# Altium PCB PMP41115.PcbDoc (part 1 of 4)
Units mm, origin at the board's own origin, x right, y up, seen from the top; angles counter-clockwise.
Board outline 97.92 x 43.13 mm, 4 copper layers (Top Layer, Signal Layer 1, Signal Layer 2, Bottom Layer), stack 1.016 mm thick; 168 components, 122 nets, 522 pads, 2459 vias.
Unrouted connection lines stored in the file: 1.
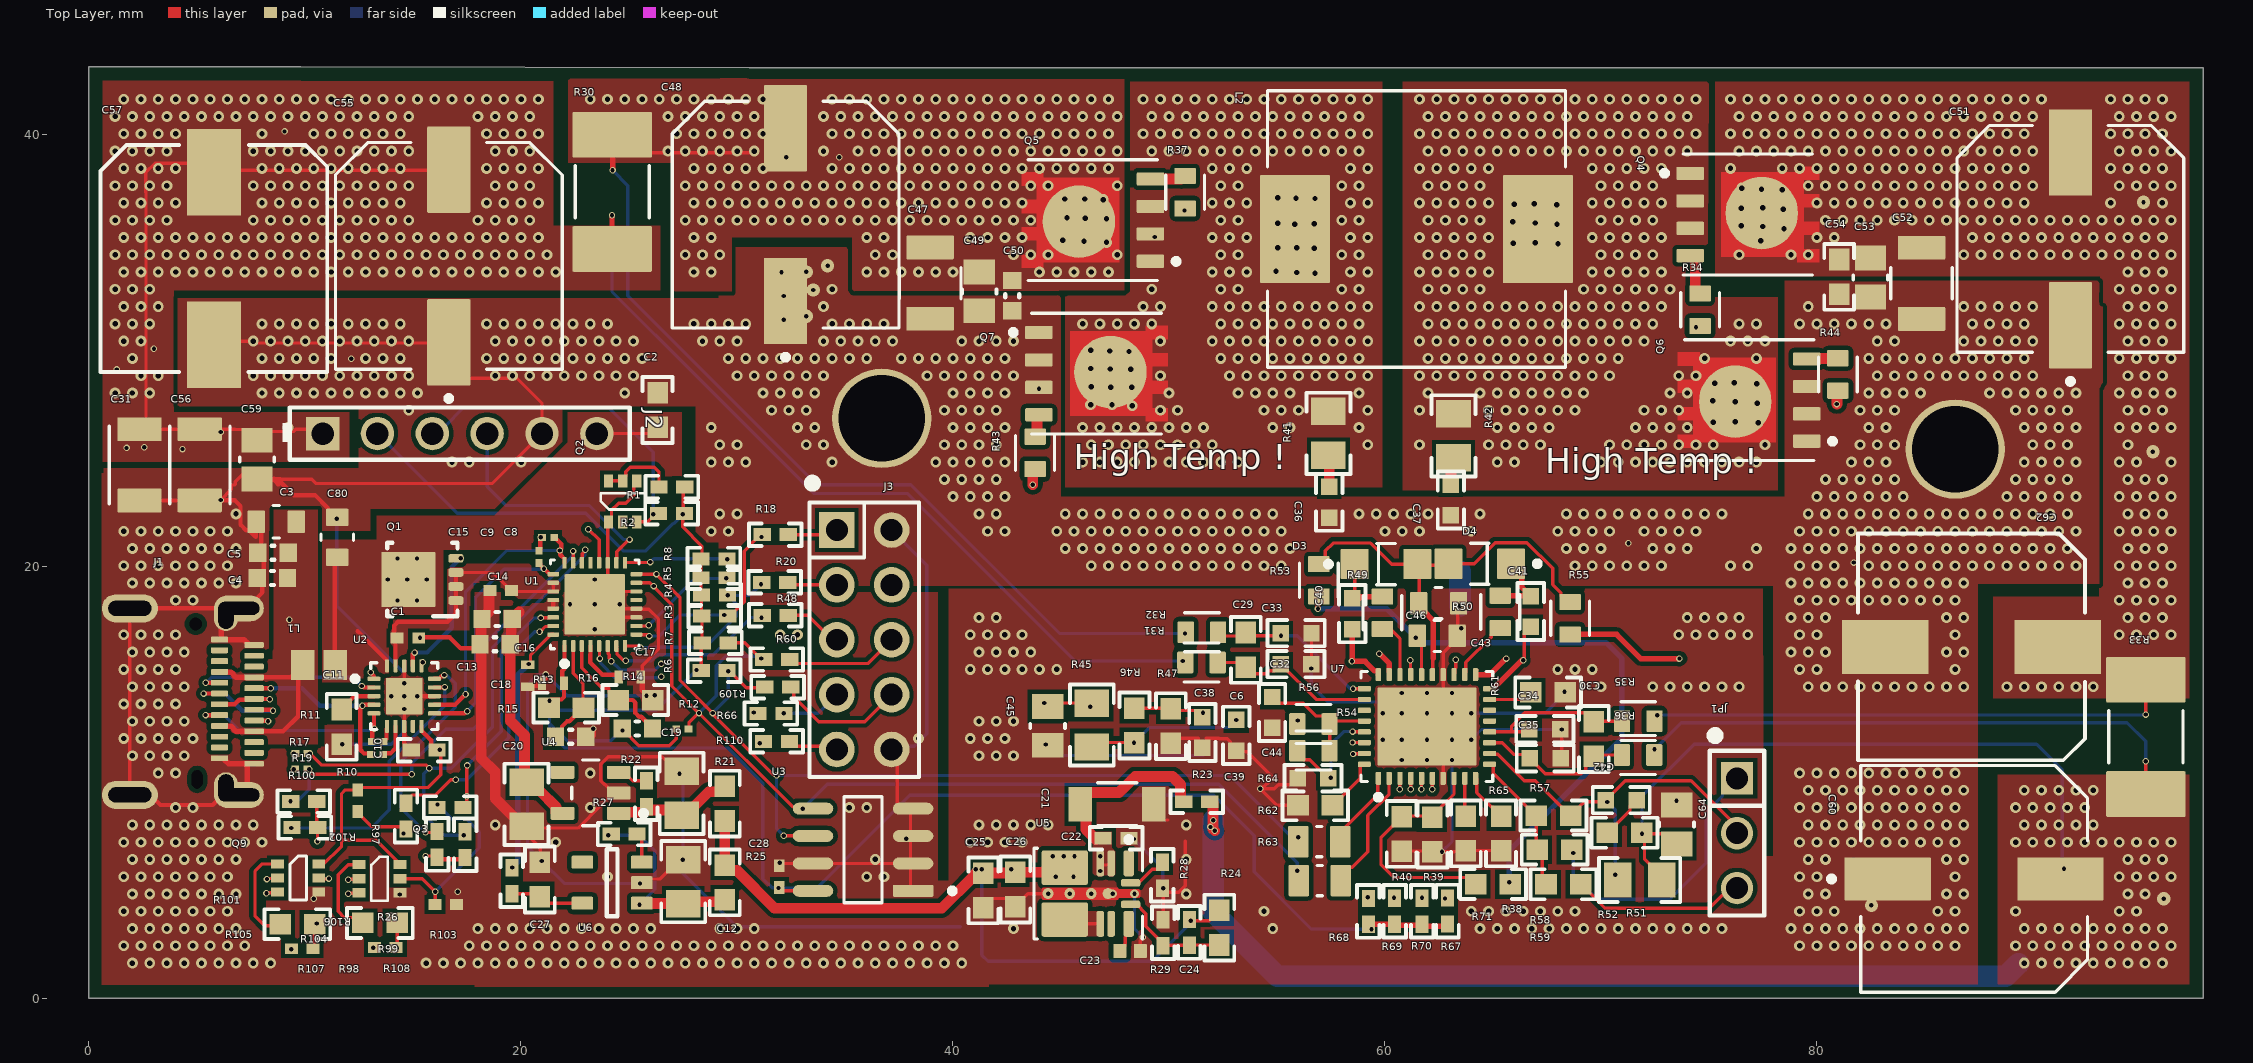
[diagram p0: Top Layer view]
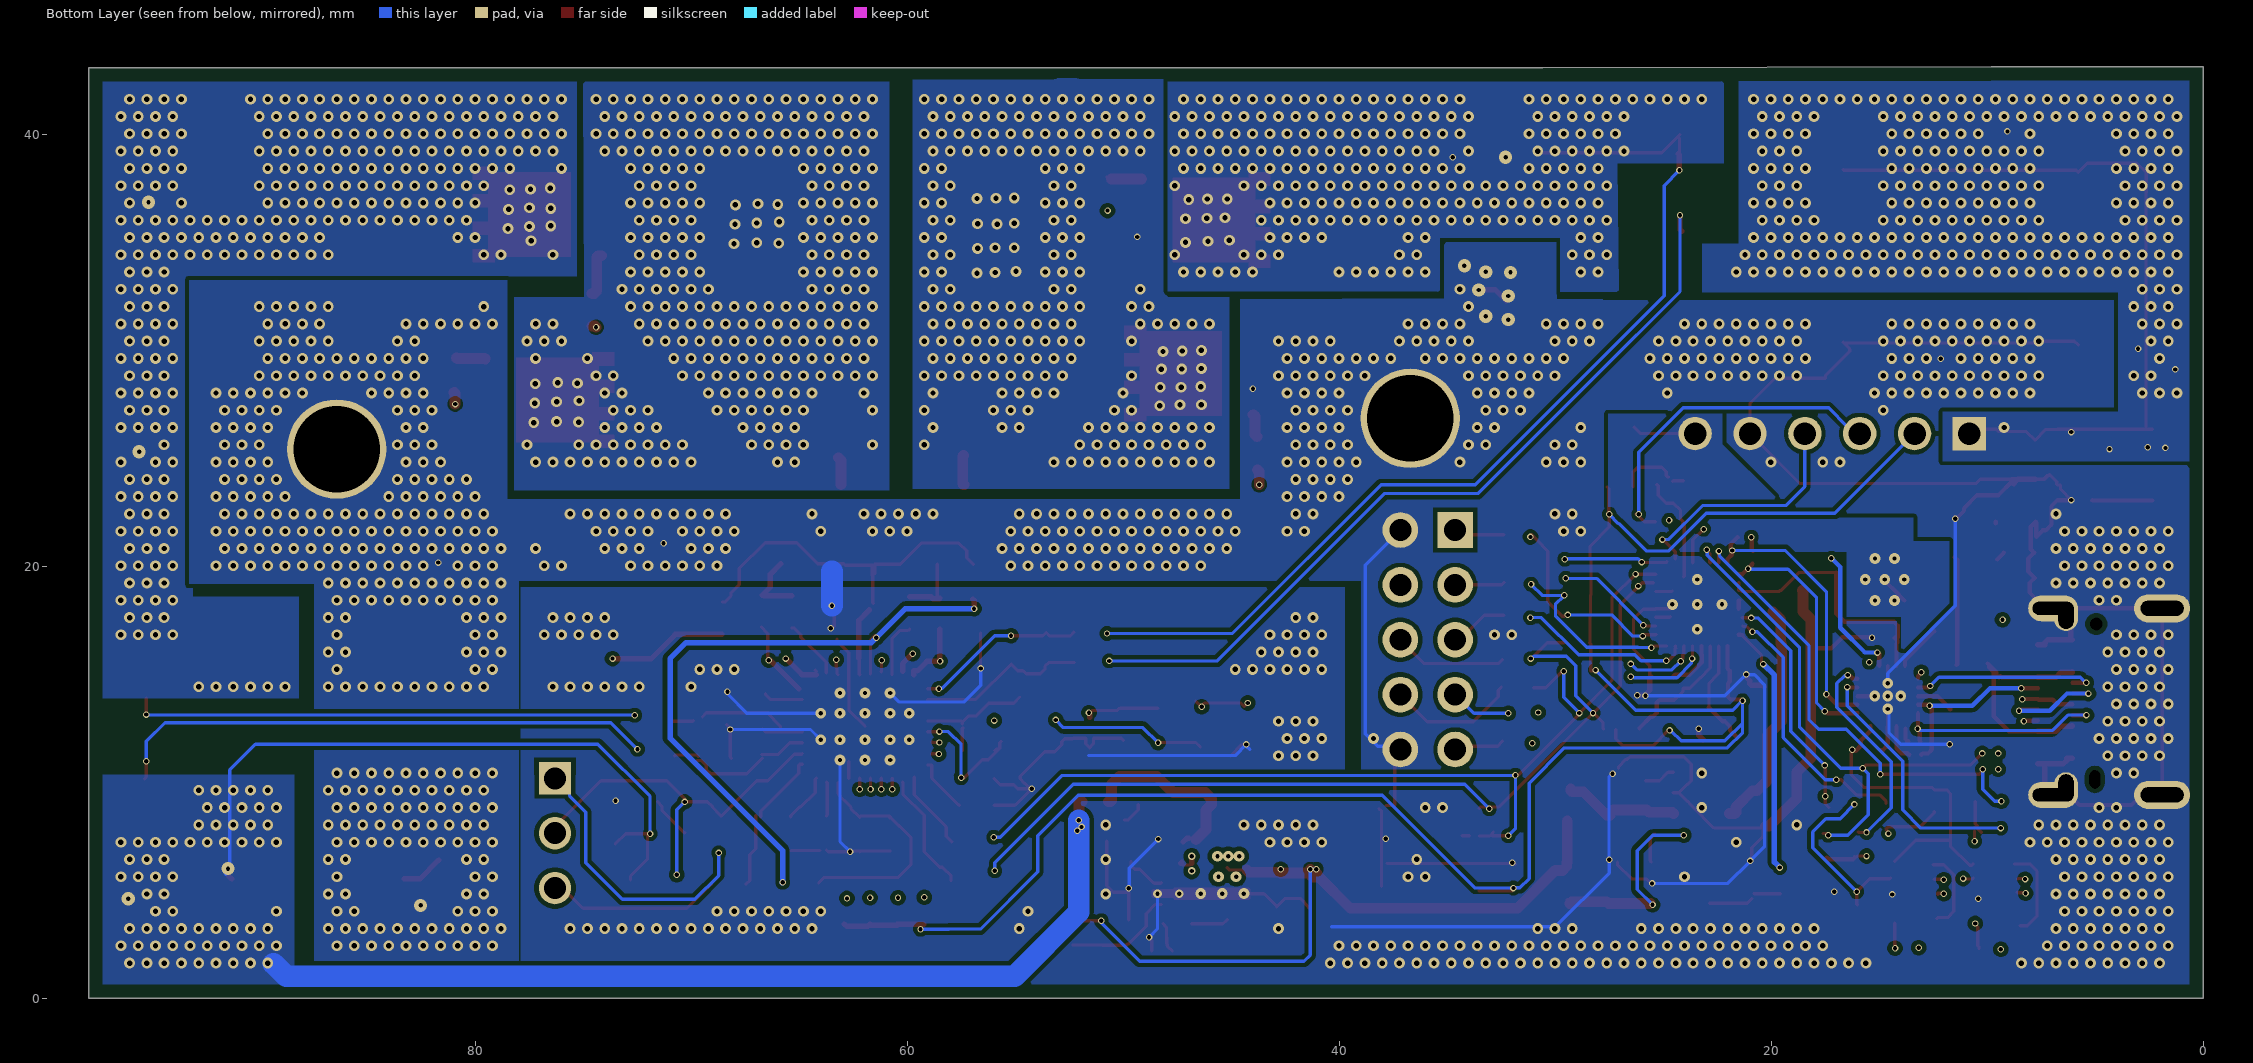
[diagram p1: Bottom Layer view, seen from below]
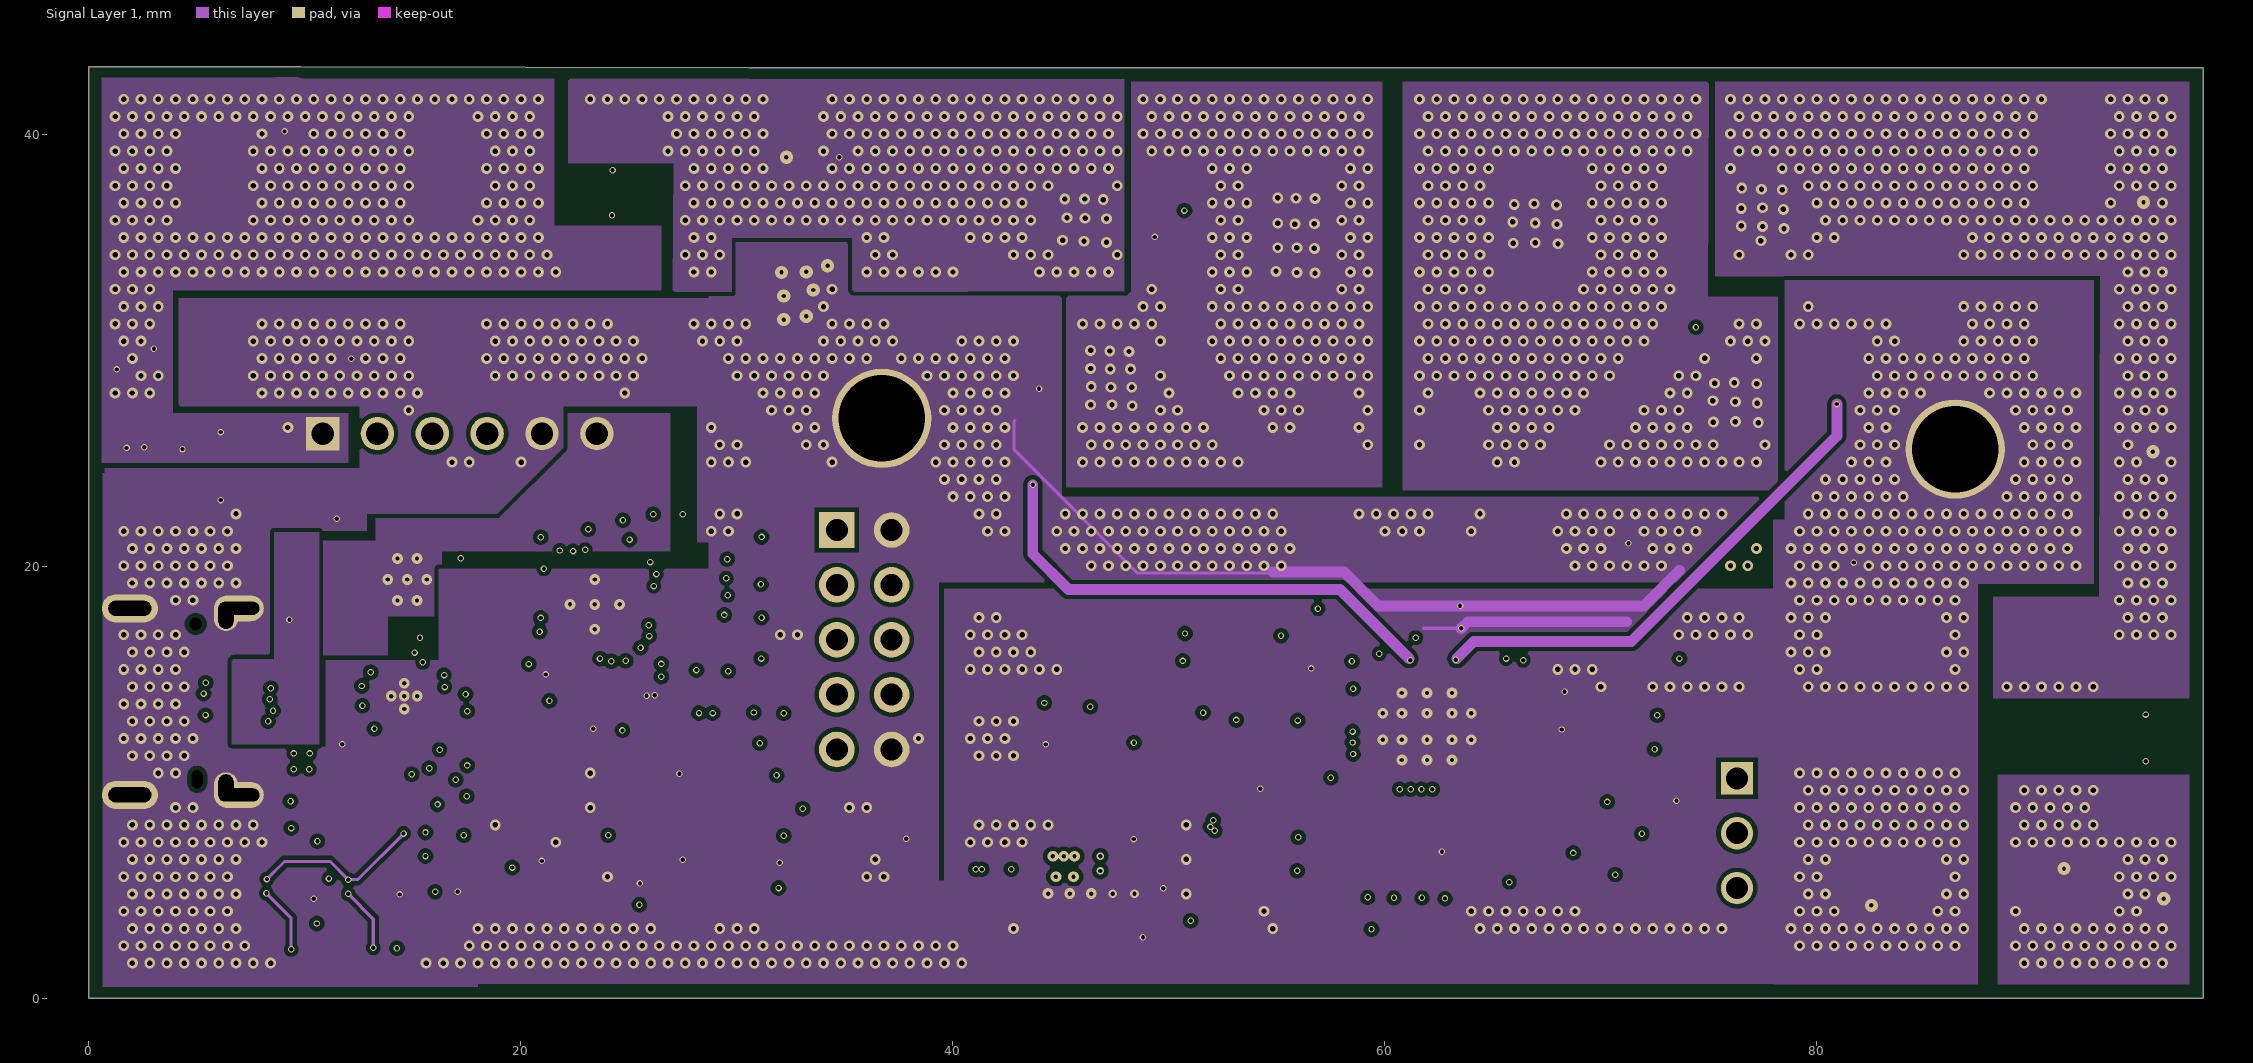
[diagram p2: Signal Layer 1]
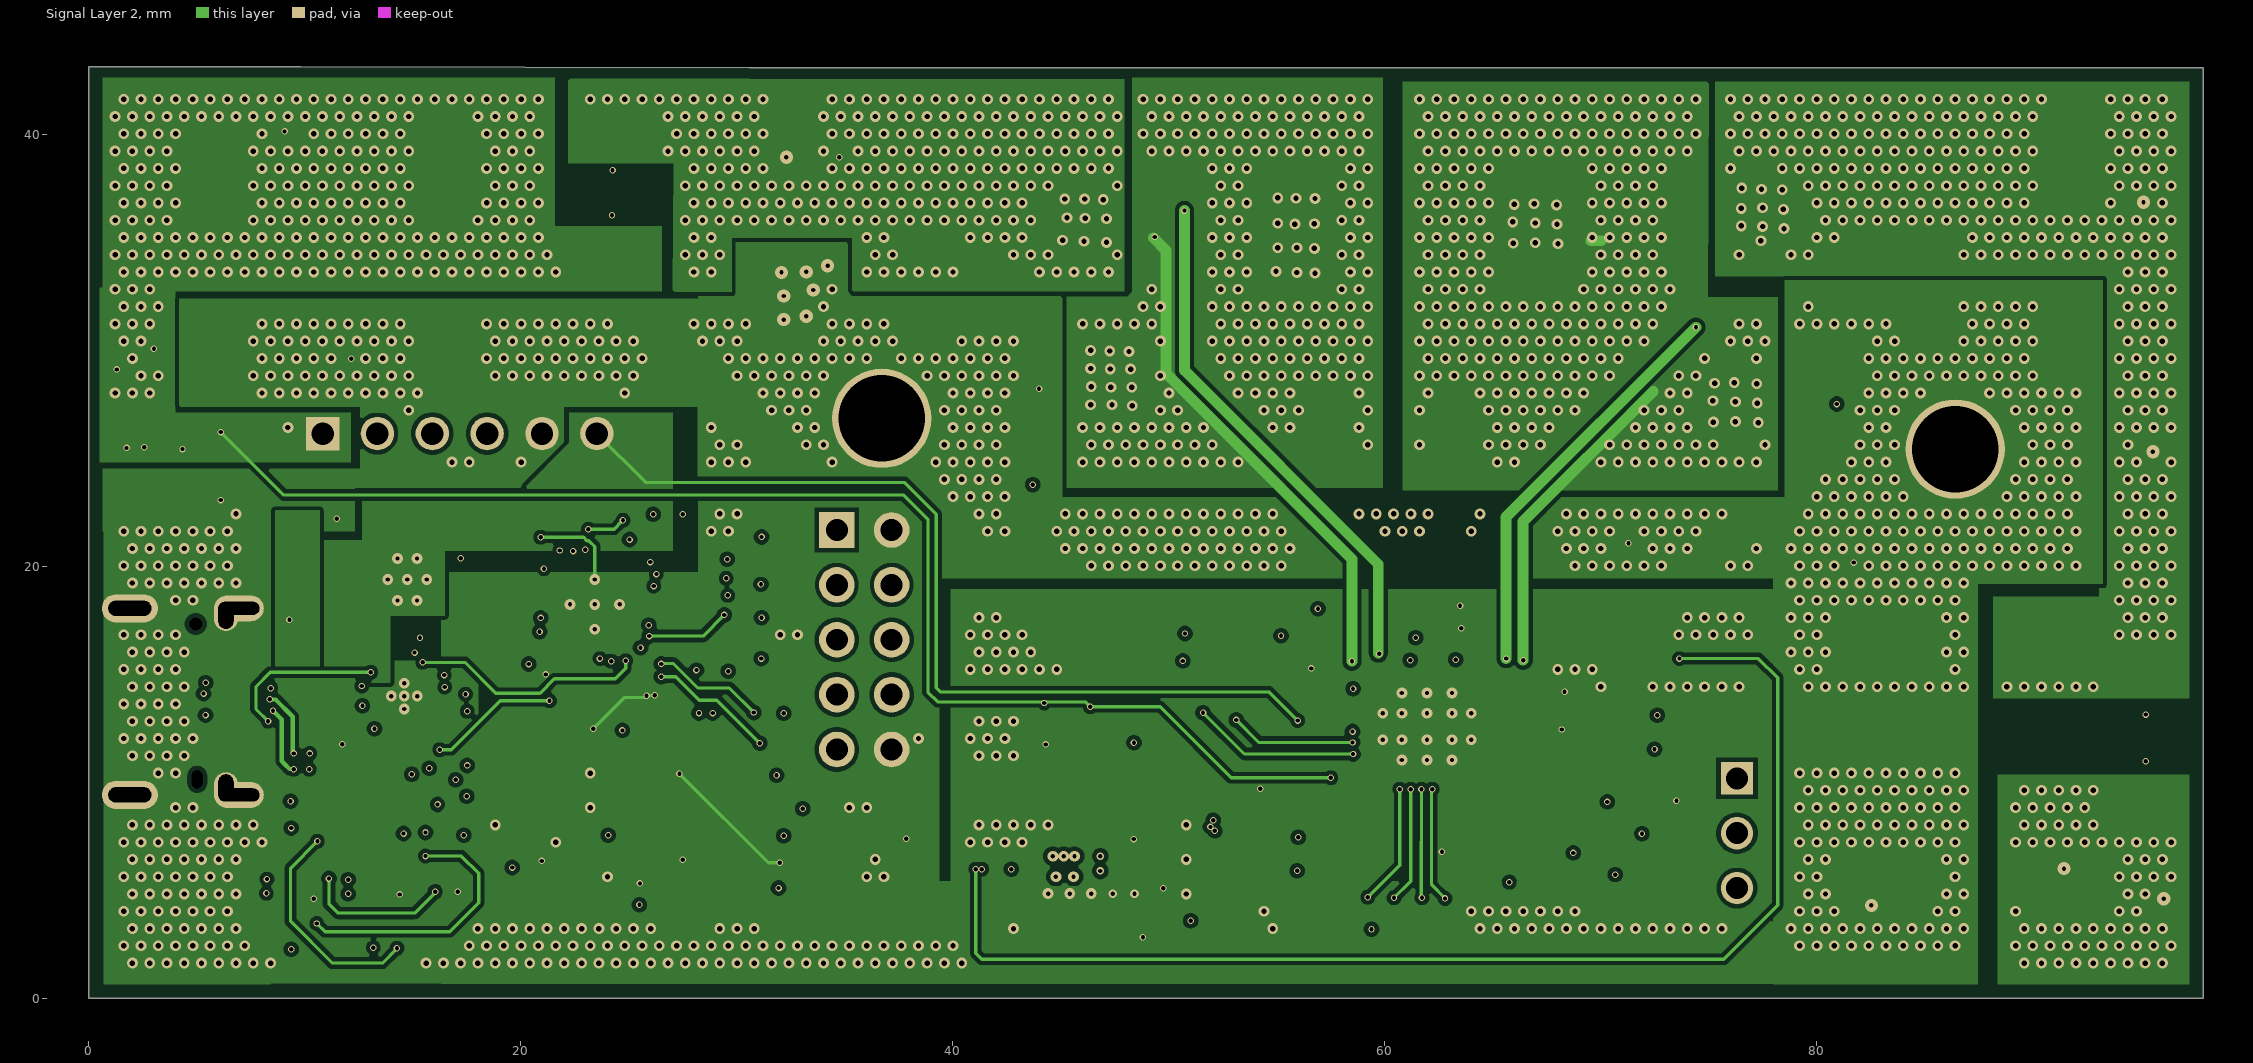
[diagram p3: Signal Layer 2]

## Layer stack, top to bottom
Top Solder: solder mask 0.0102, Solder Resist, Dk 3.5
Top Layer: signal copper 0.0356
Dielectric 1: prepreg 0.127, FR-4 High Tg, Dk 4.2
Signal Layer 1: signal copper 0.0356
Dielectric 2: core 0.6198, FR-4 High Tg, Dk 4.2
Signal Layer 2: signal copper 0.0356
Dielectric 3: prepreg 0.127, FR-4 High Tg, Dk 4.2
Bottom Layer: signal copper 0.0356
Bottom Solder: solder mask 0.0102, Solder Resist, Dk 3.5

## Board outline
0,0 0,43.129 9.83,43.129 30.582,43.078 97.917,43.078 97.917,0

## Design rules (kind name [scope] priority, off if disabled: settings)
AcuteAngle [All] p1: minimum=4.50000000000000E+0001 checktracksonly=FALSE
AssemblyTestPointUsage [All] p1: valid=2
BoardOutlineClearance BoardOutlineClearance_MountingHoles [OnCopper and InComponentClass('Mounting Holes')] p1: gap=0.5 ignorepadtopadclearanceinfootprint=FALSE
BoardOutlineClearance BoardOutlineClearance_Poly [OnCopper and IsPoly] p2: gap=0.635 ignorepadtopadclearanceinfootprint=FALSE
BoardOutlineClearance [OnCopper and Not InComponentClass('Logo') and not InComponentClass('FiducialMark') and not InRegion(1000,500,4000,800) and not InPoly] p3: gap=0.5 ignorepadtopadclearanceinfootprint=FALSE
Clearance "Stitching GND" [IsStitchingVia and InNet('GND') vs (IsVia and (Not IsStitchingVia)) Or IsPad] p1: gap=0.25 ignorepadtopadclearanceinfootprint=FALSE
Clearance Clearance_Keepouts [((IsTrack Or IsArc) And Not InPoly) And IsFree and IsKeepOut vs ((IsTrack Or IsArc) And Not InPoly) And IsFree and IsKeepOut] p2: gap=0.1 ignorepadtopadclearanceinfootprint=FALSE
Clearance Clearance_Poly [InPolygon] p3: gap=0.2 ignorepadtopadclearanceinfootprint=TRUE
Clearance Clearance_FiducialMark [IsKeepOut and InComponentClass('FiducialMark') vs IsPad and InComponentClass('FiducialMark')] p4: gap=0.1 ignorepadtopadclearanceinfootprint=FALSE
Clearance [All] p5: gap=0.2 ignorepadtopadclearanceinfootprint=TRUE
ComponentClearance ComponentClearance_MountingHoles_FiducialMarks [InComponentClass('Mounting Holes') vs InComponentClass('FiducialMark')] p1: gap=1.27 collisioncheckmode=3 verticalgap=0.254 showdistances=FALSE
ComponentClearance ComponentClearance_Shunt [InComponentClass('Header') vs InComponentClass('Shunt')] p2: gap=0 collisioncheckmode=3 verticalgap=0 showdistances=FALSE
ComponentClearance ComponentClearance_Logo [InComponentClass('Logo')] p3: gap=0.762 collisioncheckmode=3 verticalgap=0.254 showdistances=FALSE
ComponentClearance ComponentClearance_ScrewToNut [(HasFootprint('NY PMS 440 0025 PH')) vs (HasFootprint('Keystone_1902C'))] p4: gap=0.127 collisioncheckmode=3 verticalgap=0.254 showdistances=FALSE
ComponentClearance ComponentClearance_MountingHoles [InComponentClass('Mounting Holes')] p5: gap=2.54 collisioncheckmode=3 verticalgap=2540 showdistances=FALSE
ComponentClearance ComponentClearance_SmallPassives [HasFootprint('0201*') or HasFootprint('0402*') or HasFootprint('0508') or HasFootprint('0603*') or HasFootprint('0612') or HasFootprint('0805*') or HasFootprint('0815*') or HasFootprint('0830*') or HasFootprint('1206*') or HasFootprint('1210*') or HasFootprint('1808*') or HasFootprint('1812*') or HasFootprint('1825*') or HasFootprint('2010*') or HasFootprint('2220*') or HasFootprint('2225*') or HasFootprint('2512*') or HasFootprint('2728*') or HasFootprint('3518*') vs HasFootprint('0201*') or HasFootprint('0402*') or HasFootprint('0508') or HasFootprint('0603*') or HasFootprint('0612') or HasFootprint('0805*') or HasFootprint('0815*') or HasFootprint('0830*') or HasFootprint('1206*') or HasFootprint('1210*') or HasFootprint('1808*') or HasFootprint('1812*') or HasFootprint('1825*') or HasFootprint('2010*') or HasFootprint('2220*') or HasFootprint('2225*') or HasFootprint('2512*') or HasFootprint('2728*') or HasFootprint('3518*')] p6: gap=0.2 collisioncheckmode=3 verticalgap=0.254 showdistances=FALSE
ComponentClearance ComponentClearance_THtoSMT [IsThruComponent vs IsSMTComponent] p7: gap=0.762 collisioncheckmode=3 verticalgap=0.254 showdistances=FALSE
ComponentClearance ComponentClearance_THtoTH [IsThruComponent vs IsThruComponent] p8: gap=0.254 collisioncheckmode=3 verticalgap=0.254 showdistances=FALSE
ComponentClearance [All] p9: gap=0.254 collisioncheckmode=3 verticalgap=0.254 showdistances=FALSE
DiffPairsRouting [All] p1: maxlimit=2.54 minlimit=0.254 mostfreqgap=0.254 toplayer_minwidth=0.381 toplayer_maxwidth=0.381 toplayer_prefwidth=0.381 midlayer1_minwidth=0.381 midlayer1_maxwidth=0.381 midlayer1_prefwidth=0.381 midlayer2_minwidth=0.381 midlayer2_maxwidth=0.381 midlayer2_prefwidth=0.381 bottomlayer_minwidth=0.381 bottomlayer_maxwidth=0.381 bottomlayer_prefwidth=0.381 maxuncoupledlength=25.4
FabricationTestPointUsage TestPointUsage [All] p1: valid=2 allowmultiple=FALSE
FabricationTestpoint Testpoint [All] p1: side=3 testpointundercomponent=TRUE minsize=1.016 maxsize=2.54 preferedsize=1.524 minholesize=0 maxholesize=1.016 preferedholesize=0.813 testpointgrid=0.025 allowsidetop=TRUE allowsidebottom=TRUE usegrid=TRUE gridtolerance=0
FanoutControl Fanout_LCC [IsLCC] p1: bgadir=Out bgaviamode=Centered fanoutstyle=Auto fanoutdirection=Alternating viagrid=0.025 // Fanout_LCC (Default Rule)
FanoutControl Fanout_BGA [IsBGA] p2: bgadir=Out bgaviamode=Centered fanoutstyle=Auto fanoutdirection=Alternating viagrid=0.025 // Fanout_BGA (Default Rule)
FanoutControl Fanout_Default [All] p4: bgadir=Out bgaviamode=Centered fanoutstyle=Auto fanoutdirection=Alternating viagrid=0.025 // Fanout_Default (Default Rule)
FanoutControl Fanout_Small [(CompPinCount < 5)] p5: bgadir=Out bgaviamode=Centered fanoutstyle=Auto fanoutdirection=OutThenIn viagrid=0.025 // Fanout_Small (Default Rule)
HoleSize [All] p1: absolutevalues=TRUE maxlimit=6.375 minlimit=0.1 maxpercent=80.000 minpercent=20.000
MinimumAnnularRing [All] p1: minimumring=0.02
MinimumSolderMaskSliver [All] p1: minsoldermaskwidth=0.01
PlaneConnect [All] p1: planeconnectstyle=Direct reliefexpansion=0.254 reliefentries=4 reliefconductorwidth=0.254 reliefairgap=0.254
PolygonConnect [All] p1: connectstyle=Direct reliefconductorwidth=0.254 reliefentries=4 polygonreliefangle="90 Angle" airgapwidth=0.254
RoutingVias ThermalPadVias [IsVia and InAnyComponent] p1: holewidth=0.2 width=0.5 viastyle="Through Hole" minholewidth=0.1 minwidth=0.1 maxholewidth=0.33 maxwidth=0.6
RoutingVias [All] p2: holewidth=0.406 width=0.864 viastyle="Through Hole" minholewidth=0.2 minwidth=0.1 maxholewidth=1.016 maxwidth=1.651
SilkToBoardRegionClearance [Not ((IsComment or IsDesignator) And (Hide <> 'False')) and not InRegion(1000,500,4000,800)] p1:
SolderMaskExpansion [All] p1: expansion=0.05 istentingtop=FALSE
UnRoutedNet [All] p1: checkbadconnections=TRUE
Width [All] p1: maxlimit=10 minlimit=0.1 preferedwidth=0.254 checkconnectedcopper=TRUE
16 further rules are at their usual default settings.

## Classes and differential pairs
component class "U_PP5V Bias": C19 C20 C21 C22 C23 C24 C25 C26 C27 C28 R21 R22 R23 R24 R25 R26 R27 R28 R29 U4 U5 U6
net class LV: GND LODRV1 LODRV2
net class HV: ACN ACP ACUV HIDRV1 NetC36_1 NetC40_2 NetQ5_4 SW1 VSYS
net class HHV: BAT HIDRV2 NetC37_1 NetC41_1 NetQ4_4 P_OUT SRN SRP SW2
component class Header: J3 JP1
component class "U_BQ25756 Charger": C6 C29 C30 C31 C32 C33 C34 C35 C36 C37 C38 C39 C40 C41 C42 C43 C44 C45 C46 C47 C48 C49 C50 C51 C52 C53 C54 C55 C56 C57 C59 C60 C62 C64 D3 D4 JP1 L2 Q4 Q5 Q6 Q7 R30 R31 R32 R33 R34 R35 R36 R37 R38 R39 R40 R41 R42 R43 R44 R45 R46 R47 R49 R50 R51 R52 R53 R54 R55 R56 R57 R58 R59 R61 R62 R63 R64 R65 R67 R68 R69 R70 R71 U7

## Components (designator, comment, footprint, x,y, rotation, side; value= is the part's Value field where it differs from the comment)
C1 "C1005X5R1H104K050BB" 0402L 14.783,16.678 r0 top value=0.1uF
C2 "GRM188R72A104KA35J" 0603 26.344,27.234 r90 top value=0.1uF
C3 "C2012X5R2A475K125AC" FP-C2012X5R2A475K125AC_0805-MFG 8.687,22.059 r0 top value=4.7µF
C4 "C0603X103K1RACTU" 0603L 8.509,19.456 r180 top value=0.01uF
C5 "C0603X103K1RACTU" 0603L 8.534,20.625 r180 top value=0.01uF
C6 "HMK107B7104KAHT" 0603_HV 54.796,13.231 r90 top value=0.1uF
C8 "CGA1A2X7R1H221K030BA" 0201_033L 20.854,20.431 r90 top value=220pF
C9 "CGA1A2X7R1H221K030BA" 0201_033L 21.273,21.337 r180 top value=220pF
C10 "885012205037" 0402 15.533,11.483 r180 top value=0.1uF
C11 "GRM188R72A104KA35J" 0603 11.717,12.563 r90 top value=0.1uF
C12 "CGA2B3X7R1H104K050BB" 0402L 31.979,5.629 r90 top value=0.1uF
C13 "GRM188R61E106MA73D" 0603L 18.816,16.379 r180 top value=10uF
C14 "GRM188R61E106MA73D" 0603L 18.911,17.554 r180 top value=10uF
C15 "C1005X5R1H104K050BB" 0402L 19.087,18.877 r180 top value=0.1uF
C16 "CL05A106MP5NUNC" 0402_070 21.503,14.578 r0 top value=10uF
C17 "CL05A106MP5NUNC" 0402_070 25.05,14.864 r180 top value=10uF
C18 "CL05A106MP5NUNC" 0402_070 20.333,14.926 r270 top value=10uF
C19 "C2012X7S2A105K125AB" 0805_HV 27.46,9.48 r90 top value=1uF
C20 "C2012X7S2A105K125AB" 0805_HV 20.278,8.974 r270 top value=1uF
C21 "C3216X7S2A225K160AB" 1206_180 47.619,8.968 r0 top value=2.2uF
C22 "GRM155R62A104KE14D" 0402 47.57,7.402 r0 top value=0.1uF
C23 "0402YD105KAT2A" FP-0402YD105KAT2A_0402-IPC_B 48.223,2.184 r0 top value=1µF
C24 "C0402C100C8GACTU" 0402 50.965,3.043 r270 top value=10pF
C25 "CL10A226MP8NUNE" 0603 41.423,4.99 r270 top value=22uF
C26 "CL10A226MP8NUNE" 0603 42.906,5.027 r270 top value=22uF
C27 "CGA3E3X5R1A225K080AB" 0603 20.888,5.493 r90 top value=2.2uF
C28 "C2012X7S2A105K125AB" 0805_HV 27.531,5.391 r90 top value=1uF
C29 "C0603C474K4RACTU" 0603 53.581,16.129 r90 top value=0.47uF
C30 "C0603C474K4RACTU" 0603 69.694,12 r270 top value=0.47uF
C31 "GCJ32DC72A475KE01L" FP-GCJ32DC72A475KE01L_1210-MFG 2.349,24.689 r90 top value=4.7µF
C32 "HMK107B7104KAHT" 0603_HV 55.909,15.467 r0 top value=0.1uF
C33 "HMK107B7104KAHT" 0603_HV 55.912,16.902 r0 top value=0.1uF
C34 "HMK107B7104KAHT" 0603_HV 67.426,12.454 r0 top value=0.1uF
C35 "HMK107B7104KAHT" 0603_HV 67.446,11.106 r0 top value=0.1uF
C36 "06031A330JAT2A" 0603_HV 57.442,22.962 r270 top value=33pF
C37 "06031A330JAT2A" 0603_HV 63.077,23.068 r270 top value=33pF
C38 "HMK107B7104KAHT" 0603_HV 53.138,12.168 r270 top value=0.1uF
C39 "HMK107B7104KAHT" 0603_HV 51.571,12.304 r270 top value=0.1uF
C40 "06033C104KAT2A" 0603_HV 58.507,17.802 r90 top value=0.1uF
C41 "06033C104KAT2A" 0603_HV 66.774,17.897 r270 top value=0.1uF
C42 "GCM1885C2A101JA16D" 0603_HV 70.967,9.17 r180 top value=100pF
C43 "CGA4J1X7R1E475K125AE" FP-CGA4J1X7R1E475K125AE_0805-MFG 62.508,18.288 r0 top value=4.7µF
C44 "HMK107B7104KAHT" 0603_HV 56.689,10.182 r0 top value=0.1uF
C45 "08051C105K4Z2A" 0805_150 44.406,12.606 r270 top value=1uF
C46 "CGA4J1X7R1E475K125AE" FP-CGA4J1X7R1E475K125AE_0805-MFG 62.442,16.776 r0 top value=4.7µF
C47 "C3225X7R2A106K250AC" FP-C3225X7R2A106K250AC_1210-MFG 38.961,33.11 r90 top value=10µF
C48 "PCR1J101MCL1GS" FP-PCR1J101MCL1GS_SMD_RADIAL-MFG 32.268,36.279 r90 top
C49 "08051C105K4Z2A" 0805_150 41.237,32.728 r270 top value=1uF
C50 "HMK107B7104KAHT" 0603L 42.769,32.526 r270 top value=0.1uF
C51 "PCR1J101MCL1GS" FP-PCR1J101MCL1GS_SMD_RADIAL-MFG 91.764,35.157 r90 top
C52 "C3225X7R2A106K250AC" FP-C3225X7R2A106K250AC_1210-MFG 84.871,33.1 r90 top value=10µF
C53 "08051C105K4Z2A" 0805_150 82.504,33.366 r270 top value=1uF
C54 "CGA3E2C0G2A101J080AA" 0603 81.052,33.399 r270 top value=100pF
C55 "PCR1J101MCL1GS" FP-PCR1J101MCL1GS_SMD_RADIAL-MFG 16.675,34.365 r90 top
C56 "GCJ32DC72A475KE01L" FP-GCJ32DC72A475KE01L_1210-MFG 5.138,24.696 r270 top value=4.7µF
C57 "EEHZC1J560P" SM_RADIAL_10BMM 5.796,34.248 r270 top value=56uF
C59 "08051C105K4Z2A" 0805_150 7.79,24.931 r270 top value=1uF
C60 "PCR1J101MCL1GS" FP-PCR1J101MCL1GS_SMD_RADIAL-MFG 87.302,5.519 r0 top
C62 "EEHZC1J560P" SM_RADIAL_10BMM 87.182,16.262 r180 top value=56uF
C64 "08051C105K4Z2A" 0805_150 73.532,8.038 r90 top value=1uF
C80 "C2012X5R2A475K125AC" FP-C2012X5R2A475K125AC_0805-MFG 11.506,21.336 r270 top value=4.7µF
D3 "V1FM10-M3/H" FP-V1FM10-M3-H_DO-219AB-MFG 60.072,20.096 r180 top
D4 "V1FM10-M3/H" FP-V1FM10-M3-H_DO-219AB-MFG 64.412,20.114 r0 top
J1 "DX07S024JJ2R1300" JAE_DX07S024JJ2R1300 0.108,13.728 r270 top
J2 "SSW-106-01-T-S" Samtec_SSW-106-01-x-S 17.181,26.141 r0 top
J3 "PEC05DAAN" CONN_PEC05DAAN 35.912,16.594 r270 top
JP1 "PEC03SAAN" CONN_PEC03SAAN 76.325,7.635 r270 top
L1 "742792021" 0805L 10.662,15.429 r180 top value="22 ohm"
L2 "CMLB135T-100MS" FP-CMLB135T-100MS_SMT2_13MM45_12Mm6-MFG 61.481,35.612 r0 top value=10uH
Q1 "CSD18543Q3A" DNH0008A 15.449,19.384 r180 top value=60V
Q2 "2N7002DW" SOT-363 24.729,23.002 r90 top value=60V
Q3 "2N7002DW" SOT-363 13.467,5.527 r0 top value=60V
Q4 "SIR880BDP-T1-RE3" FP-SIR880BDP-T1-RE3_SO-8-MFG 76.825,36.283 r0 top
Q5 "SIR880BDP-T1-RE3" FP-SIR880BDP-T1-RE3_SO-8-MFG 46.497,36.024 r180 top
Q6 "SIR880BDP-T1-RE3" FP-SIR880BDP-T1-RE3_SO-8-MFG 76.888,27.691 r180 top
Q7 "SIR880BDP-T1-RE3" FP-SIR880BDP-T1-RE3_SO-8-MFG 46.665,28.918 r0 top
Q9 "2N7002DW" SOT-363 9.703,5.563 r0 top value=60V
R1 "ERJ-2RKF1001X" 0402 27.005,23.666 r0 top value=1.00k
R2 "ERJ-2RKF1001X" 0402 26.987,22.45 r0 top value=1.00k
R3 "RC0402FR-072K2L" 0402 28.991,17.685 r180 top value=2.20k
R4 "RC0402FR-072K2L" 0402 28.979,18.664 r180 top value=2.20k
R5 "CRCW040210K0DHEDP" 0402 28.952,19.464 r180 top value=10.0k
R6 "RC0402FR-072K2L" 0402 28.961,15.164 r180 top value=2.20k
R7 "RC0402FR-072K2L" 0402 29.017,16.45 r180 top value=2.20k
R8 "CRCW040210K0DHEDP" 0402 28.954,20.334 r180 top value=10.0k
R10 "CRCW02010000Z0ED" 0201L 13.344,11.271 r180 top value=0
R11 "CRCW02010000Z0ED" 0201L 13.383,11.887 r180 top value=0
R12 "RC0201FS-7D100KL" 0201L 27.488,12.458 r180 top value=100k
R13 "RT0603BRD07470RL" 0603 22.113,13.448 r180 top value=470
R14 "RC0603FR-07100KL" 0603L 25.405,12.483 r180 top value=100k
R15 "RC0603FR-07100KL" 0603L 22.316,12.099 r180 top value=100k
R16 "RT0603BRD07470RL" 0603 25.313,13.801 r180 top value=470
R17 "CRCW02010000Z0ED" 0201L 9.85,11.334 r180 top value=0
R18 "RC0402JR-070RL" 0402 31.795,21.459 r0 top value=0
R19 "CRCW02010000Z0ED" 0201L 9.844,10.601 r180 top value=0
R20 "RC0402JR-070RL" 0402 31.769,19.249 r0 top value=0
R21 "RC0603JR-070RL" 0603 29.455,9.003 r90 top value=0
R22 "CMP-0027004-2" 0402 25.825,9.462 r270 top value=0
R23 "CMP-0027004-2" 0402 51.307,9.092 r0 top value=0
R24 "RT0603BRD0760K4L" 0603 52.352,3.26 r90 top value=60.4k
R25 "RC0603JR-070RL" 0603 29.452,5.357 r270 top value=0
R26 "CMP-0027004-2" 0402 19.594,5.433 r270 top value=0
R27 "CMP-0027004-2" 0402 24.791,7.6 r180 top value=0
R28 "CRCW040219K6FKED" 0402 49.714,5.687 r90 top value=19.6k
R29 "ERJ-2RKF1002X" 0402 49.752,3.023 r270 top value=10.0k
R30 "WSL25125L000FEA" FP-WSL25125L000FEA_2512-MFG 24.243,37.334 r90 top value=5m
R31 "CRCW060310R0FKEB" FP-CRCW060310R0FKEB_0603-MFG 51.527,15.539 r180 top value=10
R32 "CRCW060310R0FKEB" FP-CRCW060310R0FKEB_0603-MFG 51.548,16.944 r180 top value=10
R33 "WSL25125L000FEA" FP-WSL25125L000FEA_2512-MFG 95.26,12.096 r270 top value=5m
R34 "CRCW06030000Z0EA" FP-CRCW06031R50FKEAHP_0603-MFG 74.615,31.873 r270 top value=0
R35 "CRCW060310R0FKEB" FP-CRCW060310R0FKEB_0603-MFG 71.753,12.823 r180 top value=10
R36 "CRCW060310R0FKEB" FP-CRCW060310R0FKEB_0603-MFG 71.743,11.258 r180 top value=10
R37 "CRCW06030000Z0EA" FP-CRCW06031R50FKEAHP_0603-MFG 50.768,37.313 r270 top value=0
R38 "RC0603FR-075K23L" 0603 65.033,5.273 r0 top value=5.23k
R39 "ERJ-3EKF1002V" 0603 62.223,7.577 r90 top value=10.0k
R40 "RC0603FR-0730K1L" 0603 60.8,7.607 r90 top value=30.1k
R41 "RC0805JR-072R2L" 0805_HV 57.406,26.15 r90 top value=2.2
R42 "RC0805JR-072R2L" 0805_HV 63.198,26.036 r90 top value=2.2
R43 "CRCW06030000Z0EA" FP-CRCW06031R50FKEAHP_0603-MFG 43.822,25.246 r90 top value=0
R44 "CRCW06030000Z0EA" FP-CRCW06031R50FKEAHP_0603-MFG 80.994,28.878 r90 top value=0
R45 "CRCW08051M00FKEAC" 0805_HV 46.452,12.645 r90 top value=1.00Meg
R46 "RT0603BRD07383KL" 0603 48.421,12.62 r270 top value=383k
R47 "RT0603BRD0731K2L" 0603 50.112,12.595 r90 top value=31.2k
R48 "RC0402JR-070RL" 0402 31.795,17.725 r0 top value=0
R49 "CRCW06030000Z0EA" FP-CRCW06031R50FKEAHP_0603-MFG 59.903,17.84 r90 top value=0
R50 "CRCW06030000Z0EA" FP-CRCW06031R50FKEAHP_0603-MFG 65.362,17.885 r90 top value=0
R51 "CRCW06031R10JNEA" 0603 71.115,7.656 r0 top value=1.1
R52 "ERJ-PB6B2493V" 0805_HV 71.816,5.469 r0 top value=249k
R53 "CRCW06030000Z0EA" FP-CRCW06031R50FKEAHP_0603-MFG 56.961,19.346 r90 top value=0
R54 "CRCW06030000Z0EA" FP-CRCW06031R50FKEAHP_0603-MFG 56.712,11.463 r0 top value=0
R55 "CRCW06030000Z0EA" FP-CRCW06031R50FKEAHP_0603-MFG 68.595,17.591 r90 top value=0
R56 "CRCW06030000Z0EA" FP-CRCW06031R50FKEAHP_0603-MFG 56.71,12.693 r0 top value=0
R57 "RT0603BRD0713K7L" 0603 67.826,8.45 r0 top value=13.7k
R58 "RT0603BRD0730K5L" 0603 67.879,6.873 r0 top value=30.5k
R59 "RT0603BRD0713KL" 0603 68.282,5.272 r0 top value=13.0k
R60 "RC0402JR-070RL" 0402 31.858,15.676 r180 top value=0
R61 "CRCW06033K01FKEA" 0603 67.578,14.156 r180 top value=3.01k
R62 "RC0603FR-07100KL" 0603 56.796,8.925 r0 top value=100k
R63 "CRCW08050000Z0EA" FP-CRCW080510R0JNEAHP_0805-MFG 57.009,5.44 r180 top value=0
R64 "CRCW08050000Z0EA" FP-CRCW080510R0JNEAHP_0805-MFG 56.98,7.242 r180 top value=0
R65 "RC0603FR-073K6L" 0603 65.399,7.627 r90 top value=3.60k
R66 "RC0402JR-070RL" 0402 31.592,13.178 r0 top value=0
R67 "RC0402FR-0710K5L" 0402 62.921,4.031 r270 top value=10.5k
R68 "RC0402FR-0710K5L" 0402 59.254,4.015 r270 top value=10.5k
R69 "RC0402FR-0710K5L" 0402 60.47,4.023 r270 top value=10.5k
R70 "RC0402FR-0710K5L" 0402 61.743,4.023 r270 top value=10.5k
R71 "RG1608P-822-B-T5" 0603 63.767,7.63 r90 top value=8.20k
R97 "RC1005F104CS" 0402L 12.459,9.138 r90 top value=100k
R98 "RC0402JR-070RL" 0402 14.695,8.429 r270 top value=0
R99 "RC0402JR-070RL" 0402 17.433,7.107 r270 top value=0
R100 "RC0402JR-070RL" 0402 9.962,9.107 r180 top value=0
R101 "RG1608P-2493-B-T5" 0603 9.661,3.425 r180 top value=249k
R102 "RG1608P-2493-B-T5" 0603 13.483,3.48 r180 top value=249k
R103 "RC0402JR-070RL" 0402 16.133,7.117 r270 top value=0
R104 "RC0402JR-070RL" 0402 10.013,7.903 r180 top value=0
R105 "ERJ-2RKF1004X" 0402L 9.886,2.285 r0 top value=1.00Meg
R106 "ERJ-2RKF1004X" 0402L 13.74,2.348 r0 top value=1.00Meg
R107 "RC0402JR-070RL" 0402 16.732,8.825 r180 top value=0
R108 "RC1005F104CS" 0402L 16.532,4.33 r180 top value=100k
R109 "RC0402JR-070RL" 0402 31.902,14.402 r180 top value=0
R110 "RC0402JR-070RL" 0402 31.852,11.887 r0 top value=0
U1 "TPS26750RSMR" RSM0032B-MFG 23.435,18.232 r90 top
U2 "TPD4S480RUKR" RUK0020B-MFG 14.61,13.984 r0 top
U3 "CAT24C512WI-GT3" FP-CAT24C512WI-GT3_SOIC8-IPC_C 35.857,6.871 r180 top
U4 "TPS7A2450DBVR" DBV0005A-MFG 23.24,9.503 r180 top
U5 "TPSM365R6RDNR" RDN0011A-MFG 46.195,4.839 r270 top
U6 "TPS76333DBVR" DBV0005A_N 24.237,5.344 r180 top
U7 "BQ25756RRVT" RRV0036A-MFG 61.968,12.578 r90 top

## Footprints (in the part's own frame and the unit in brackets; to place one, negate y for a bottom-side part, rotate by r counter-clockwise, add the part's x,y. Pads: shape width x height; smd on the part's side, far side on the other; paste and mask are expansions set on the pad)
0201_033L [mm] "0201"
  rect 0.36x0.32 smd mask+0.048: 1(-0.28,0) 2(0.28,0)
  body extent -0.31,-0.16 0.31,0.16, height 0.33
0201L [mm] "Data from Kemet datasheet CC101_COM dated 7/28/11"
  rect 0.36x0.32 smd mask+0.048: 1(-0.28,0) 2(0.28,0)
  body extent -0.31,-0.16 0.31,0.16, height 0.26
0402 [mm] "0402 from SM-752 data"
  rect 0.8x0.6 smd: 1(-0.6,0) 2(0.6,0)
  silkscreen extent -1.22,-0.52 1.22,0.52, body extent -0.55,-0.3 0.55,0.3, height 0.6
0402_070 [mil] "SMD, 2-Leads, Body 1.2x0.7mm, Height 0.7mm"
  rect 15x24 smd: 1(-20,0) 2(20,0)
  body extent -24,-14 24,14, height 28
0402L [mm] "0402 from SM-752 data"
  rect 0.6x0.5 smd: 1(-0.5,0) 2(0.5,0)
  body extent -0.55,-0.3 0.55,0.3, height 0.6
0603 [mm] "0603 from SM-752 data"
  rect 1x0.95 smd: 1(-0.8,0) 2(0.8,0)
  silkscreen extent -1.52,-0.69 1.52,0.69, body extent -0.87,-0.47 0.87,0.47, height 1
0603_HV [mil] "Ernesto recommended land pattern.  26 mil between pads."
  rect 30x30 smd: 1(-28,0) 2(28,0)
  silkscreen extent -52,-24 52,24, body extent -34,-19 34,19, height 39
0603L [mm] "0603 from SM-752 data"
  rect 0.8x0.85 smd: 1(-0.7,0) 2(0.7,0)
  silkscreen extent -0.07,-0.33 0.07,0.33, body extent -0.87,-0.47 0.87,0.47, height 1
0805_150 [mm] "0805 / 1.5 mm height"
  rect 1.15x1.45 smd: 1(-0.9,0) 2(0.9,0)
  silkscreen extent -0.1,-0.8 0.1,0.8, body extent -1.1,-0.72 1.1,0.72, height 1.5
0805_HV [mil] "0805 with 30mil clearance between pads"
  rect 50x63 smd: 1(-40,0) 2(40,0)
  silkscreen extent -74,-40 74,40, body extent -43,-29 43,29, height 57
0805L [mm] "0805 from SM-752 data"
  rect 1.1x1.4 smd: 1(-0.75,0) 2(0.75,0)
  body extent -1.1,-0.72 1.1,0.72, height 1.45
1206_180 [mm] "1206_180"
  rect 1.1x1.6 smd: 1(-1.7,0) 2(1.7,0)
  silkscreen extent -0.9,-1 0.9,1, body extent -1.75,-0.95 1.75,0.95, height 1.8
CONN_PEC03SAAN [mm] "SULLINS"
  rect 1.5x1.5 hole 1.016: 1(-2.54,0)
  round 1.5 hole 1.016: 2(0,0) 3(2.54,0)
  silkscreen extent -4.72,-1.27 3.81,1.27, body extent -3.84,-1.3 3.84,1.3, height 8.38
CONN_PEC05DAAN [mm] "SULLINS"
  rect 1.65x1.65 hole 1.016 mask+0: 1(-5.08,-1.27)
  round 1.65 hole 1.016 mask+0: 2(-5.08,1.27) 3(-2.54,-1.27) 4(-2.54,1.27) 5(0,-1.27) 6(0,1.27) 7(2.54,-1.27) 8(2.54,1.27) 9(5.08,-1.27) 10(5.08,1.27)
  silkscreen extent -7.45,-2.6 6.35,2.54, body extent -6.35,-2.54 6.35,2.54, height 8.38
DBV0005A-MFG [mm]
  rrect17% 1.1x0.6 smd paste+0 mask+0: 1(-1.3,0.95) 2(-1.3,0) 3(-1.3,-0.95) 4(1.3,-0.95) 5(1.3,0.95)
  silkscreen extent -2.58,-1.53 0.87,1.53, body extent -1.95,-1.78 1.95,1.78, height 0.25
DBV0005A_N [mm] "SOT23, 5-Leads, Body 2.9x1.6mm, Pitch 0.95mm, Lead Span 2.8mm, IPC Medium Density"
  rrect17% 1x0.6 smd: 1(-1.375,0.95) 2(-1.375,0) 3(-1.375,-0.95) 4(1.375,-0.95) 5(1.375,0.95)
  silkscreen extent -0.25,-1.55 0.25,1.55, body extent -1.42,-1.46 1.42,1.46, height 1.09
DNH0008A [mm] "VSONP-8"
  rrect50% 0.7x0.4 smd paste-0.05 mask-0.05: 1(-1.55,0.975) 2(-1.55,0.325) 3(-1.55,-0.325) 4(-1.55,-0.975) 5(1.55,-0.975) 6(1.55,-0.325) 7(1.55,0.325) 8(1.55,0.975)
  rrect4% 2.51x2.55 smd paste-1.5 mask-1.5: 9(0.645,0)
  rrect14% 0.705x1.125 on Top Paste: 9A(-0.208,0.662) 9B(0.697,0.662) 9C(-0.208,-0.663) 9D(0.697,-0.663)
  silkscreen extent -1.62,-1.7 1.62,1.7, body extent -1.65,-1.65 1.65,1.66, height 0.91
FP-0402YD105KAT2A_0402-IPC_B [mm]
  rrect16% 0.608x0.658 smd paste+0 mask+0: 1(-0.475,0) 2(0.475,0)
  body extent -0.5,-0.25 0.5,0.25, height 0.56
FP-C2012X5R2A475K125AC_0805-MFG [mm]
  rrect13% 0.8x1.05 smd paste+0 mask+0: 1(-0.925,0) 2(0.925,0)
  silkscreen extent -0.15,-0.75 0.15,0.75, body extent -1.43,-0.85 1.43,0.85, height 0.25
FP-C3225X7R2A106K250AC_1210-MFG [mm]
  rrect9% 1.1x2.2 smd paste+0 mask+0: 1(-1.65,0) 2(1.65,0)
  silkscreen extent -0.72,-1.43 0.72,1.43, body extent -1.6,-1.25 1.6,1.25, height 2.85
FP-CAT24C512WI-GT3_SOIC8-IPC_C [mm]
  rrect18% 1.874x0.545 smd paste+0 mask+0: 1(-2.316,1.905)
  rrect100% 1.874x0.545 smd paste+0 mask+0: 2(-2.316,0.635) 3(-2.316,-0.635) 4(-2.316,-1.905) 5(2.316,-1.905) 6(2.316,-0.635) 7(2.316,0.635) 8(2.316,1.905)
  silkscreen extent -4.25,-2.45 0.88,2.45, body extent -3.35,-2.55 3.35,2.55, height 0.25
FP-CGA4J1X7R1E475K125AE_0805-MFG [mm]
  rrect13% 0.8x1.05 smd paste+0 mask+0: 1(-0.925,0) 2(0.925,0)
  silkscreen extent -0.15,-0.72 0.15,0.72, body extent -1.43,-0.82 1.43,0.82, height 0.25
FP-CMLB135T-100MS_SMT2_13MM45_12Mm6-MFG [mm]
  rrect3% 3.25x5 smd paste+0 mask+0: 1(-5.625,0) 2(5.625,0)
  silkscreen extent -6.9,-6.4 6.9,6.4, body extent -7.35,-6.5 7.35,6.5, height 0.25
FP-CRCW06031R50FKEAHP_0603-MFG [mm]
  rrect13% 0.75x1 smd paste+0 mask+0: 1(-0.75,0) 2(0.75,0)
  silkscreen extent -0.8,-0.9 0.8,0.9, body extent -0.8,-0.43 0.8,0.43, height 0.55
FP-CRCW060310R0FKEB_0603-MFG [mm]
  rrect13% 0.75x1 smd paste+0 mask+0: 1(-0.75,0) 2(0.75,0)
  silkscreen extent -0.8,-0.9 0.8,0.9, body extent -1.22,-0.6 1.22,0.6, height 0.25
FP-CRCW080510R0JNEAHP_0805-MFG [mm]
  rrect11% 0.95x1.45 smd paste+0 mask+0: 1(-0.975,0) 2(0.975,0)
  silkscreen extent -0.13,-0.7 0.13,0.7, body extent -1.55,-0.82 1.55,0.82, height 0.25
FP-GCJ32DC72A475KE01L_1210-MFG [mm]
  rrect9% 1.1x2.05 smd paste+0 mask+0: 1(-1.65,0) 2(1.65,0)
  silkscreen extent -1.8,-1.4 1.8,1.4, body extent -1.6,-1.25 1.6,1.25, height 2.3
FP-PCR1J101MCL1GS_SMD_RADIAL-MFG [mm]
  rrect5% 4x2 smd paste+0 mask+0: 1(-4,0) 2(4,0)
  silkscreen extent -6.72,-5.25 5.25,5.25, body extent -6.25,-5.5 6.25,5.5, height 0.25
FP-SIR880BDP-T1-RE3_SO-8-MFG [mil]
  rrect16% 50x24 smd paste+0 mask+0: 1(-105,75) 2(-105,25) 3(-105,-25) 4(-105,-75)
  round 132.13 smd paste+0 mask+0: 5-6-7-8(25.41,2.72)
  Top Layer region: -48,77 90,77 90,87 130,87 130,63 102,63 102,37 130,37 130,13 102,13 102,-13 130,-13 130,-37 102,-37 102,-63 130,-63 130,-87 90,-87 90,-77 -48,-77
  silkscreen extent -157,-110 118,110, body extent -120,-102 122,101, height 46
FP-V1FM10-M3-H_DO-219AB-MFG [mm]
  rrect8% 1.3x1.4 smd paste+0 mask+0: 1(1.45,0) 2(-1.45,0)
  silkscreen extent -0.43,-0.95 2.79,0.95, body extent -2.2,-1.05 2.2,1.05, height 0.25
FP-WSL25125L000FEA_2512-MFG [mm]
  rrect5% 2.11x3.68 smd paste+0 mask+0: 1(-2.645,0) 2(2.645,0)
  silkscreen extent -1.21,-1.72 1.21,1.72, body extent -3.8,-1.94 3.8,1.94, height 0.25
JAE_DX07S024JJ2R1300 [mm] "Receptacle, USB 3.1 Type C, R/A, SMT"
  rrect37% 0.27x0.9 smd: A1(-2.625,7.55) A2(-2.125,7.55) A3(-1.625,7.55) A4(-1.125,7.55) A5(-0.625,7.55) A6(-0.125,7.55) A7(0.375,7.55) A8(0.875,7.55) A9(1.375,7.55) A10(1.875,7.55) A11(2.375,7.55) A12(2.875,7.55)
  round 0.3 hole 0.6 unplated mask+0.102: ALIGN1(-3.6,4.85)
  rrect100% 0.55x0.3 hole 0.5 slot 0.85 at 0 deg unplated mask+0.102: ALIGN2(3.6,4.915)
  rrect37% 0.27x0.8 smd: B1(2.625,5.95) B2(2.125,5.95) B3(1.625,5.95) B4(1.125,5.95) B5(0.625,5.95) B6(0.125,5.95) B7(-0.375,5.95) B8(-0.875,5.95) B9(-1.375,5.95) B10(-1.875,5.95) B11(-2.375,5.95) B12(-2.875,5.95)
  rrect100% 1.2x2.3 hole 0.6 slot 1.9 at 90 deg: S1(-4.32,6.85) S2(4.32,6.85)
  rrect100% 1.45x1.1 hole 0.7 slot 1.25 at 0 deg: S1(-3.995,6.25) S2(3.995,6.25)
  rrect100% 1.3x2.6 hole 0.7 slot 2 at 90 deg: S3(-4.32,1.8) S4(4.32,1.8)
  body extent -4.47,-0.5 4.47,7.67, height 3.14
RDN0011A-MFG [mm]
  rrect42% 1.2x0.475 smd paste-1000 mask-1000: 1(-1.4,1.962) 8(1.4,1.962)
  rrect57% 1.2x0.35 smd paste-1000 mask-1000: 2(-1.4,1.15) 3(-1.4,0.65) 6(1.4,0.65) 7(1.4,1.15)
  rrect13% 1.6x2.15 smd paste-1000 mask-1000: 4(-1.2,-1) 5(1.2,-1)
  rrect57% 0.35x0.9 smd paste-1000 mask-1000: 9(0.5,2.05) 11(-0.5,2.05)
  round 0.504 smd paste-1000 mask-1000: 10(0,1.005)
  Top Layer region: -0.2,2.4 -0.187,2.45 -0.15,2.487 -0.1,2.5 -0.1,2.5 0.1,2.5 0.15,2.487 0.187,2.45 0.2,2.4 0.2,2.4 0.2,1.515 0.203,1.5 0.212,1.487 0.225,1.478 0.24,1.475 0.24,1.475 0.24,1.475 0.26,1.47 0.275,1.455 0.28,1.435 0.28,1.435 0.28,-1.975 0.267,-2.025 0.23,-2.062 0.18,-2.075 0.18,-2.075 -0.18,-2.075 -0.23,-2.062 -0.267,-2.025 -0.28,-1.975 -0.28,-1.975 -0.28,1.435 -0.275,1.455 -0.26,1.47 -0.24,1.475 -0.24,1.475 -0.24,1.475 -0.225,1.478 -0.212,1.487 -0.203,1.5 -0.2,1.515 -0.2,1.515
  silkscreen extent -2.62,-2.42 2.1,2.6, body extent -1.75,-2.25 1.75,2.25, height 2.1
RRV0036A-MFG [mm]
  rrect40% 0.6x0.25 smd paste+0 mask+0: 1(-2.4,2.25) 2(-2.4,1.75) 3(-2.4,1.25) 4(-2.4,0.75) 5(-2.4,0.25) 6(-2.4,-0.25) 7(-2.4,-0.75) 8(-2.4,-1.25) 9(-2.4,-1.75) 10(-2.4,-2.25) 19(2.4,-2.25) 20(2.4,-1.75) 21(2.4,-1.25) 22(2.4,-0.75) 23(2.4,-0.25) 24(2.4,0.25) 25(2.4,0.75) 26(2.4,1.25) 27(2.4,1.75) 28(2.4,2.25)
  rrect40% 0.25x0.6 smd paste+0 mask+0: 11(-1.75,-2.9) 12(-1.25,-2.9) 13(-0.75,-2.9) 14(-0.25,-2.9) 15(0.25,-2.9) 16(0.75,-2.9) 17(1.25,-2.9) 18(1.75,-2.9) 29(1.75,2.9) 30(1.25,2.9) 31(0.75,2.9) 32(0.25,2.9) 33(-0.25,2.9) 34(-0.75,2.9) 35(-1.25,2.9) 36(-1.75,2.9)
  rrect3% 3.6x4.6 smd paste-1000 mask+0: 37(0,0)
  silkscreen extent -3.4,-3.05 2.55,3.05, body extent -2.8,-3.3 2.8,3.3, height 0.25
RSM0032B-MFG [mm]
  rrect50% 0.55x0.2 smd paste+0 mask+0: 1(-1.925,1.4) 2(-1.925,1) 3(-1.925,0.6) 4(-1.925,0.2) 5(-1.925,-0.2) 6(-1.925,-0.6) 7(-1.925,-1) 8(-1.925,-1.4) 17(1.925,-1.4) 18(1.925,-1) 19(1.925,-0.6) 20(1.925,-0.2) 21(1.925,0.2) 22(1.925,0.6) 23(1.925,1) 24(1.925,1.4)
  rrect50% 0.2x0.55 smd paste+0 mask+0: 9(-1.4,-1.925) 10(-1,-1.925) 11(-0.6,-1.925) 12(-0.2,-1.925) 13(0.2,-1.925) 14(0.6,-1.925) 15(1,-1.925) 16(1.4,-1.925) 25(1.4,1.925) 26(1,1.925) 27(0.6,1.925) 28(0.2,1.925) 29(-0.2,1.925) 30(-0.6,1.925) 31(-1,1.925) 32(-1.4,1.925)
  rrect4% 2.8x2.8 smd paste-1000 mask+0: 33(0,0)
  silkscreen extent -2.87,-2.05 2.05,2.05, body extent -2.3,-2.3 2.3,2.3, height 0.25
RUK0020B-MFG [mm]
  rrect50% 0.6x0.2 smd paste+0 mask+0: 1(-1.4,0.8) 2(-1.4,0.4) 3(-1.4,0) 4(-1.4,-0.4) 5(-1.4,-0.8) 11(1.4,-0.8) 12(1.4,-0.4) 13(1.4,0) 14(1.4,0.4) 15(1.4,0.8)
  rrect50% 0.2x0.6 smd paste+0 mask+0: 6(-0.8,-1.4) 7(-0.4,-1.4) 8(0,-1.4) 9(0.4,-1.4) 10(0.8,-1.4) 16(0.8,1.4) 17(0.4,1.4) 18(0,1.4) 19(-0.4,1.4) 20(-0.8,1.4)
  rrect6% 1.7x1.7 smd paste-1000 mask+0: 21(0,0)
  silkscreen extent -2.4,-1.55 1.55,1.55, body extent -1.8,-1.8 1.8,1.8, height 0.25
Samtec_SSW-106-01-x-S [mm] "Receptacle, 6x1, 2.54mm, TH"
  rect 1.55x1.55 hole 1.04: 1(-6.35,0)
  round 1.55 hole 1.04: 2(-3.81,0) 3(-1.27,0) 4(1.27,0) 5(3.81,0) 6(6.35,0)
  silkscreen extent -8.2,-1.21 7.87,1.21, body extent -7.87,-1.21 7.87,1.21, height 8.51
SM_RADIAL_10BMM [mm] "Nichicon 10x10"
  rect 4x2.5 smd: 1(-4,0) 2(4,0)
  silkscreen extent -5.25,-5.25 5.25,5.25, body extent -5.25,-5.25 5.25,5.25, height 10.5
SOT-363 [mm]
  rect 0.6x0.42 smd mask+0.051: 1(-0.95,0.65) 2(-0.95,0) 3(-0.95,-0.65) 4(0.95,-0.65) 5(0.95,0) 6(0.95,0.65)
  silkscreen extent -0.38,-1.02 0.38,1.02, body extent -1.1,-1.1 1.1,1.1, height 1.12

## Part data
C1 C15: library part CMP-0006279-2, "CAP, CERM, 0.1 uF, 50 V, +/- 10%, X5R, 0402", Cap_Case=0402, Manufacturer=TDK, Supplier Part Number 1=445-5942-1-ND, TempCo=X5R, Tolerance_%=10%, Value1="0.039064 ohm", Value2=50V, ValueDisplayed=0.1uF
C2 C11: library part CMP-0007470-4, "CAP, CERM, 0.1 uF, 100 V, +/- 10%, X7R, 0603", Cap_Case=0603, Manufacturer=MuRata, Supplier Part Number 1=490-6439-1-ND, TempCo=X7R, Tolerance_%=10%, Value1=Unknown, Value2=100V, ValueDisplayed=0.1uF
C3 C80: library part CMP-0098058-1, "4.7 µF ±10% 100V Ceramic Capacitor X5R 0805 (2012 Metric)", Digikey Part Number=445-C2012X5R2A475K125ACCT-ND, Manufacturer=TDK, Mouser Part Number=810-C2012X5R2A475K12, Operating Temperature Range="-55°C to +85°C", TempCo=15%, Temperature Characteristic=X5R, Tolerance_%=10%, ValueDisplayed=4.7uF
C4 C5: library part CMP-0006977-4, "CAP, CERM, 0.01 uF, 100 V, +/- 10%, X7R, 0603", Cap_Case=0603, Manufacturer=Kemet, Supplier Part Number 1=399-5347-1-ND, TempCo=X7R, Tolerance_%=10%, Value1=Unknown, Value2=100V, ValueDisplayed=0.01uF
C6 C32 C33 C34 C35 C38 C39 C44 C50: library part CMP-0081011-1, "CAP, CERM, 0.1 µF, 100 V,+/- 10%, X7R, AEC-Q200 Grade 1, 0603", Cap_Case=0603, Manufacturer="Taiyo Yuden", Supplier Part Number 1=587-6009-1-ND, TempCo=X7R, Tolerance_%=10%, Value2=100V, ValueDisplayed=0.1µF
C8 C9: library part CMP-0009652-3, "CAP, CERM, 220 pF, 50 V, +/- 10%, X7R, AEC-Q200 Grade 1, 0201", Cap_Case=0201_033, Manufacturer=TDK, Supplier Part Number 1=445-12109-1-ND, TempCo=X7R, Tolerance_%=10%, Value1="11.6275 ohm", Value2=50V, ValueDisplayed=220pF
C10: library part CMP-0006228-1, "CAP, CERM, 0.1 uF, 16 V, +/- 10%, X7R, 0402", Cap_Case=0402, Manufacturer="Wurth Elektronik", Supplier Part Number 1=732-7532-1-ND, TempCo=X7R, Tolerance_%=10%, Value1=Unknown, Value2=16V, ValueDisplayed=0.1uF
C12: library part CMP-0006325-2, "CAP, CERM, 0.1 uF, 50 V, +/- 10%, X7R, AEC-Q200 Grade 1, 0402", Cap_Case=0402, Manufacturer=TDK, Supplier Part Number 1=445-6899-1-ND, TempCo=X7R, Tolerance_%=10%, Value1="0.039064 ohm", Value2=50V, ValueDisplayed=0.1uF
C13 C14: library part CMP-0007344-5, "CAP, CERM, 10 uF, 25 V, +/- 20%, X5R, 0603", Cap_Case=0603, Manufacturer=MuRata, Supplier Part Number 1=490-7202-1-ND, TempCo=X5R, Tolerance_%=20%, Value1=Unknown, Value2=25V, ValueDisplayed=10uF
C16 C17 C18: library part CMP-0006339-4, "CAP, CERM, 10 uF, 10 V, +/- 20%, X5R, 0402", Cap_Case=0402, Manufacturer="Samsung Electro-Mechanics", TempCo=X5R, Tolerance_%=20%, Value1=Unknown, Value2=10V, ValueDisplayed=10uF
C19 C20 C28: library part CMP-0007891-2, "CAP, CERM, 1 uF, 100 V, +/- 10%, X7S, 0805", Cap_Case=0805, Manufacturer=TDK, Supplier Part Number 1=445-5205-1-ND, TempCo=X7S, Tolerance_%=10%, Value1="0.008255 ohm", Value2=100V, ValueDisplayed=1uF
C21: library part CMP-0008724-2, "CAP, CERM, 2.2 uF, 100 V, +/- 10%, X7S, 1206", Cap_Case=1206_180, Manufacturer=TDK, Supplier Part Number 1=445-5207-1-ND, TempCo=X7S, Tolerance_%=10%, Value1="0.005718 ohm", Value2=100V, ValueDisplayed=2.2uF
C22: library part CMP-0006618-1, "CAP, CERM, 0.1 uF, 100 V, +/- 10%, X5R, 0402", Cap_Case=0402, Manufacturer=MuRata, Supplier Part Number 1=490-10458-1-ND, TempCo=X5R, Tolerance_%=10%, Value1=Unknown, Value2=100V, ValueDisplayed=0.1uF
C23: library part CMP-00860000-2, "CAPACITOR, X5R, 0402, 16V, 1UF", Manufacturer=AVX, TempCo=15%, Tolerance_%=10%
C24: library part CMP-0064914-1, "CAP, CERM, 10 pF, 10 V,+/- 2.5%, C0G/NP0, 0402", Cap_Case=0402, Manufacturer=Kemet, Supplier Part Number 1=399-8939-1-ND, TempCo=C0G/NP0, Tolerance_%=2.5%, Value1=Unknown, Value2=10V, ValueDisplayed=10pF
C25 C26: library part CMP-0007108-2, "CAP, CERM, 22 uF, 10 V, +/- 20%, X5R, 0603", Cap_Case=0603, Manufacturer="Samsung Electro-Mechanics", TempCo=X5R, Tolerance_%=20%, Value1=Unknown, Value2=10V, ValueDisplayed=22uF
C27: library part CMP-0007091-5, "CAP, CERM, 2.2 uF, 10 V, +/- 10%, X5R, AEC-Q200 Grade 3, 0603", Cap_Case=0603, Manufacturer=TDK, Supplier Part Number 1=445-12444-1-ND, TempCo=X5R, Tolerance_%=10%, Value1=Unknown, Value2=10V, ValueDisplayed=2.2uF
C29 C30: library part CMP-0006944-4, "CAP, CERM, 0.47 uF, 16 V, +/- 10%, X7R, 0603", Cap_Case=0603, Manufacturer=Kemet, Supplier Part Number 1=399-4922-1-ND, TempCo=X7R, Tolerance_%=10%, Value1=Unknown, Value2=16V, ValueDisplayed=0.47uF
C31 C56: library part CMP-0093675-1, "4.7uF ±10% 100V Ceramic Capacitor X7S 1210 (3225 Metric)", Manufacturer=Murata, Operating Temperature Range="-55°C to +125°C", TempCo=22%, Temperature Characteristic=X7S, Tolerance_%=10%, ValueDisplayed=4.7uF
C36 C37: library part CMP-0006722-4, "CAP, CERM, 33 pF, 100 V, +/- 5%, C0G/NP0, 0603", Cap_Case=0603, Manufacturer=AVX, Supplier Part Number 1=478-1143-1-ND, TempCo=C0G/NP0, Tolerance_%=5%, Value1="0.209 ohm", Value2=100V, ValueDisplayed=33pF
C40 C41: library part CMP-0006753-4, "CAP, CERM, 0.1 uF, 25 V, +/- 10%, X7R, 0603", Cap_Case=0603, Manufacturer=AVX, Supplier Part Number 1=478-3714-1-ND, TempCo=X7R, Tolerance_%=10%, Value1="0.05 ohm", Value2=25V, ValueDisplayed=0.1uF
C42: library part CMP-0007130-4, "CAP, CERM, 100 pF, 100 V, +/- 5%, C0G/NP0, AEC-Q200 Grade 1, 0603", Cap_Case=0603, Manufacturer=MuRata, Supplier Part Number 1=490-4771-1-ND, TempCo=C0G/NP0, Tolerance_%=5%, Value1=Unknown, Value2=100V, ValueDisplayed=100pF
C43 C46: library part CMP-0093626-1, "Cap Ceramic 4.7uF 25V X7R 10% Pad SMD 0805 +125°C Automotive T/R", Manufacturer="TDK Corporation", Operating Temperature Range="-55°C to +125°C", TempCo=15%, Temperature Characteristic=X7R, Tolerance_%=0.1%, ValueDisplayed=4.7uF
C45 C49 C53 C59 C64: library part CMP-0861070-1, "CAP, CERM, 1 µF, 100 V,+/- 10%, X7R, AEC-Q200 Grade 1, 0805", Cap_Case=0805, Manufacturer=AVX, TempCo=X7R, Tolerance_%=10%, Value2=100V, ValueDisplayed=1µF
C47 C52: library part CMP-0096021-1, "10 µF ±10% 100V Ceramic Capacitor X7R 1210 (3225 Metric)", Digikey Part Number=445-C3225X7R2A106K250ACCT-ND, Manufacturer=TDK, Mouser Part Number=810-C3225X7R2A106K25, Operating Temperature Range="-55°C to +125°C", TempCo=15%, Temperature Characteristic=X7R, Tolerance_%=10%, ValueDisplayed=10uF
C48 C51 C55 C60: library part CMP-0089206-1, "100uF 63V Polymer ALUM Electrolytic Capacitor, CR Series 4000h 10.3x10.3x12.6mm", Digikey Part Number=493-13783-1-ND, Leakage Current=189uA, Manufacturer=Nichicon, Mouser Part Number=647-PCR1J101MCL1GS, Operating Temperature Range="-55°C to +125°C", Tolerance_%=20%, ValueDisplayed=100uF
C54: library part CMP-0007237-3, "Multilayer Ceramic Capacitors MLCC - SMD/SMT CGA 0603 100V 100pF C0G 5% AEC-Q200", Cap_Case=0603, Manufacturer=TDK, Supplier Part Number 1=490-1351-1-ND, TempCo=C0G/NP0, Tolerance_%=5%, Value1=Unknown, Value2=100V, ValueDisplayed=100pF
C57 C62: library part CMP-0012603-3, "CAP, Polymer Hybrid, 56 uF, 63 V, +/- 20%, 30 ohm, 10x10 SMD", Manufacturer=Panasonic, Supplier Part Number 1=P15469CT-ND, Tolerance_%=20%, Value1="30 ohm", Value2=63V, ValueDisplayed=56uF
D3 D4: library part CMP-0093639-2, "Diode Schottky 1A Surface Mount DO-219AB (SMF)", Digikey Part Number=112-V1FM10-M3/HCT-ND, Forward Current=1A, Manufacturer=Vishay, Max Surge Forward Current=30A, Mouser Part Number=78-V1FM10-M3/H, Operating Temperature Range="-40°C to +175°C", Peak Reverse Current=0.2uA, ValueDisplayed=95pF
J1: library part CMP-0085712-2, "Receptacle, USB 3.1 Type C, R/A, Gold, SMT", Color=Black, Current_A=1.25A, Manufacturer="JAE Electronics", Voltage_V=20V
J2: library part CMP-0075621-1, "Receptacle, 6x1, 2.54mm, Tin, TH", Color=Black, Current_A=5.7A, Manufacturer=Samtec, Supplier Part Number 1=SAM1213-06-ND
J3: library part CMP-0054550-2, "Header, 100mil, 5x2, Tin, TH", Color=Black, Current_A=3A, Manufacturer="Sullins Connector Solutions", Supplier Part Number 1=S2012E-05-ND, Voltage_V=1.8kV
JP1: library part CMP-0002338-1, "Header, 100mil, 3x1, Tin, TH", Color=Black, Current_A=3A, Manufacturer="Sullins Connector Solutions", Supplier Part Number 1=S1012E-03-ND, Voltage_V=1.8kV
L1: library part CMP-0003072-1, "Ferrite Bead, 22 ohm @ 100 MHz, 6 A, 0805", Manufacturer="Wurth Elektronik", Supplier Part Number 1=732-4637-1-ND, Value1="0.008 ohm", Value2=6A, ValueDisplayed="22 ohm"
L2: library part CMP-0096007-1, "Power Choke Coil 10uH 20% 9A 22mOhm", Manufacturer=Cyntec, Operating Temperature Range="-55°C to +125°C", Test Frequency=100kHz, Tolerance_%=20%
Q1: library part CMP-0000826-2, "MOSFET, N-CH, 60 V, 35 A, DNH0008A (VSONP-8)", Alternate Manufacturer=None, Manufacturer="Texas Instruments", Supplier Part Number 1=CSD18543Q3A-ND, Value1=0.01, Value2="11.1 nC"
Q2 Q3 Q9: library part CMP-0000770-1, "MOSFET, 2-CH, N-CH, 60 V, 0.115 A, SOT-363", Alternate Manufacturer=None, Manufacturer="Fairchild Semiconductor", Supplier Part Number 1=2N7002DWCT-ND
Q4 Q5 Q6 Q7: library part CMP-0096839-1, "N-Channel 80 V 18.6A (Ta), 70.6A (Tc) 5W (Ta), 71.4W (Tc) Surface Mount PowerPAK® SO-8", Digikey Part Number=742-SIR880BDP-T1-RE3CT-ND, Drain To Source Breakdown Voltage=80V, Input Capacitace At Vds="2930pF @ 40V", Manufacturer=Vishay, Mouser Part Number=78-SIR880BDP-T1-RE3, Operating Temperature Range="-55°C to +150°C", Power_W=5W, Pulse Drain Current=200A, Typ Forward Diode Voltage=0.74V
R1 R2: library part CMP-0026657-1, "RES, 1.00 k, 1%, 0.1 W, 0402", Manufacturer=Panasonic, Power_W=100mW, Supplier Part Number 1=P1.00KLCT-ND, TempCo="100 ppm/C", Tolerance_%=1%, Value2=0.1W, Value_Code=1k00, ValueDisplayed=1.00k
R3 R4 R6 R7: library part CMP-0026729-1, "RES, 2.20 k, 1%, 0.063 W, 0402", Manufacturer="Yageo America", Power_W=63mW, Supplier Part Number 1=311-2.20KLRCT-ND, TempCo="100 ppm/C", Tolerance_%=1%, Value2=0.063W, Value_Code=2k20, ValueDisplayed=2.20k
R5 R8: library part CMP-0026769-1, "RES, 10.0 k, 0.5%, 0.063 W, 0402", Manufacturer=Vishay-Dale, Power_W=63mW, Supplier Part Number 1=541-10KAVCT-ND, TempCo="50 ppm/C", Tolerance_%=0.5%, Value2=0.063W, Value_Code=10k0, ValueDisplayed=10.0k
R10 R11 R17 R19: library part CMP-0027008-4, "RES, 0, 5%, 0.05 W, 0201", Manufacturer=Vishay-Dale, Power_W=50mW, Supplier Part Number 1=72M6743, TempCo=ppm/C, Tolerance_%=5%, Value2=0.05W, Value_Code=0000, ValueDisplayed=0
R12: library part CMP-0028069-1, "RES, 100 k, 1%, 0.05 W, 0201", Manufacturer="Yageo America", Power_W=50mW, Supplier Part Number 1=603-RC0201FS-7D100KL, TempCo="200 ppm/C", Tolerance_%=1%, Value2=0.05W, Value_Code=100k
R13 R16: library part CMP-0024263-1, "RES, 470, 0.1%, 0.1 W, 0603", Manufacturer="Yageo America", Power_W=100mW, TempCo="25 ppm/C", Tolerance_%=0.1%, Value2=0.1W, Value_Code=470R, ValueDisplayed=470
R14 R15 R62: library part CMP-0022735-5, "RES, 100 k, 1%, 0.1 W, 0603", Manufacturer=Yageo, Power_W=100mW, Supplier Part Number 1=311-100KHRCT-ND, TempCo="100 ppm/C", Tolerance_%=1%, Value2=0.1W, Value_Code=100k
R18 R20 R48 R60 R66 R98 R99 R100 R103 R104 R107 R109 R110: library part CMP-0027004-1, "RES, 0, 5%, 0.063 W, 0402", Manufacturer="Yageo America", Power_W=63mW, Supplier Part Number 1=311-0.0JRCT-ND, TempCo="200 ppm/C", Tolerance_%=5%, Value2=0.063W, Value_Code=0000, ValueDisplayed=0
R21 R25: library part CMP-0025885-5, "RES, 0, 5%, 0.1 W, 0603", Manufacturer=Yageo, Power_W=100mW, Supplier Part Number 1=311-0.0GRCT-ND, TempCo="200 ppm/C", Tolerance_%=5%, Value2=0.1W, Value_Code=0000, ValueDisplayed=0
R22 R23 R26 R27: "RES, 0, 5%, 0.063 W, 0402", Manufacturer="Yageo America", PartNumber=RC0402JR-070RL, Power_W=63mW, Supplier Part Number 1=311-0.0JRCT-ND, TempCo="200 ppm/C", Tolerance_%=5%, Value2=0.063W, Value_Code=0000, ValueDisplayed=0
R24: library part CMP-0024382-2, "RES, 60.4 k, 0.1%, 0.1 W, 0603", Manufacturer="Yageo America", Power_W=100mW, TempCo="25 ppm/C", Tolerance_%=0.1%, Value2=0.1W, Value_Code=60k4, ValueDisplayed=60.4k
R28: library part CMP-0026068-2, "RES, 19.6 k, 1%, 0.063 W, 0402", Manufacturer=Vishay-Dale, Power_W=63mW, Supplier Part Number 1=541-19.6KLCT-ND, TempCo="100 ppm/C", Tolerance_%=1%, Value2=0.063W, Value_Code=19k6, ValueDisplayed=19.6k
R29: library part CMP-0026658-1, "RES, 10.0 k, 1%, 0.1 W, 0402", Manufacturer=Panasonic, Power_W=100mW, Supplier Part Number 1=P10.0KLCT-ND, TempCo="100 ppm/C", Tolerance_%=1%, Value2=0.1W, Value_Code=10k0, ValueDisplayed=10.0k
R30 R33: library part CMP-0096841-1, "Res Metal Strip 2512 0.005 Ohm 1% 1W 110ppm/C Molded SMD SMD Embossed Plastic T/R", Digikey Part Number=WSLG-.005CT-ND, Manufacturer=Vishay, Mouser Part Number=71-WSL25125L000FEA, Octopart Part Number=dd8716d1bbbb0240, Operating Temperature Range="-65°C to +170°C", Power_W=1W, TempCo=110ppm/°C, Tolerance_%=1%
